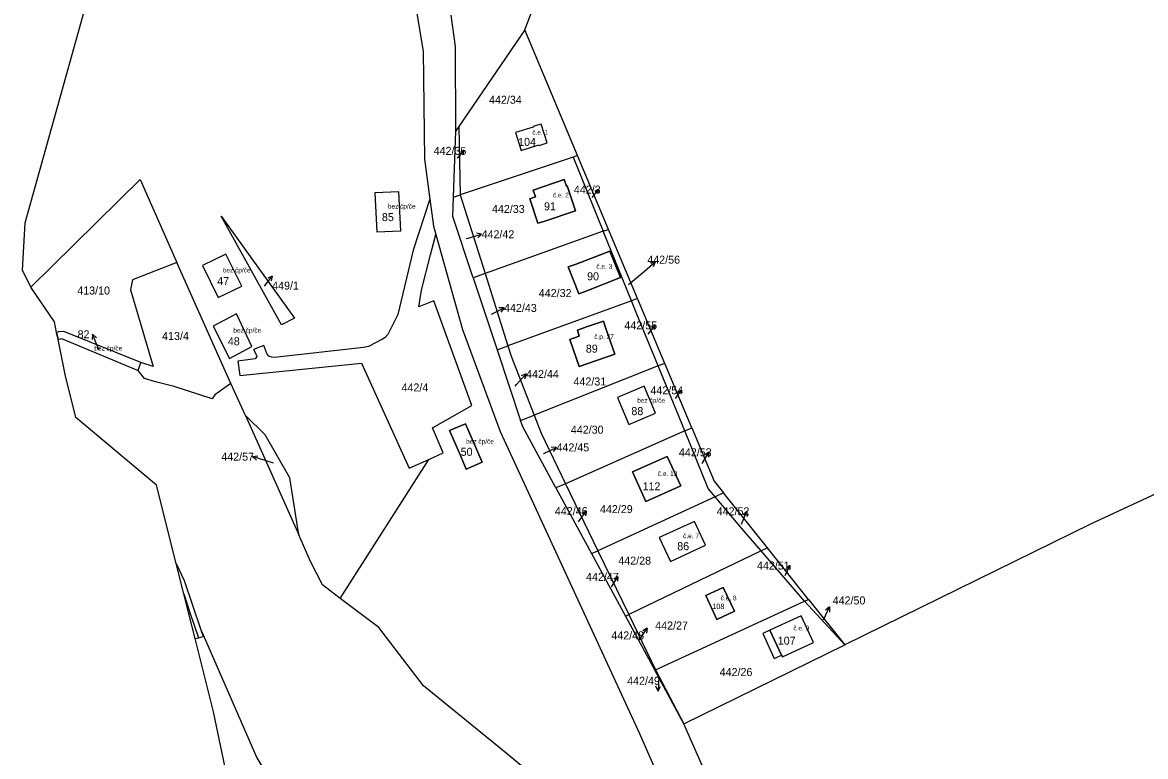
# Model space of a CAD drawing. Extents: x -880531 to -877616, y -1023932 to -1021350.
# Drawn here: x -880276 to -880037.5, y -1022931.1 to -1022775.2 of the extents above; entities that cross this region are included whole.
import ezdxf

# ---------------------------------------------------------------- set-up
doc = ezdxf.new("R2010")
doc.units = 0
for name, color, linetype in [('Definiční body', 7, 'Continuous'), ('Hranice parcel', 7, 'Continuous'), ('Parcelní čísla', 7, 'Continuous'), ('Polygon budovy', 7, 'Continuous'), ('Pop  PČ popisy', 7, 'Continuous'), ('Vnitřní kresba', 7, 'Continuous')]:
    doc.layers.add(name, color=color, linetype=linetype)

msp = doc.modelspace()

# ---------------------------------------------------------------- linework, layer by layer
at = {"layer": 'Hranice parcel'}
for p, q in [((-880169.29, -1022776.73), (-880144.75, -1022711.36)), ((-880169.29, -1022776.73), (-880183.31, -1022797.24)), ((-880158.09, -1022803.43), (-880169.29, -1022776.73)), ((-880184.42, -1022812.24), (-880183.96, -1022798.18)), ((-880183.31, -1022797.24), (-880183.96, -1022798.18)), ((-880183.31, -1022797.24), (-880183.01, -1022811.77)), ((-880159.04, -1022803.75), (-880183.01, -1022811.77)), ((-880158.09, -1022803.43), (-880159.04, -1022803.75)), ((-880159.04, -1022803.75), (-880152.64, -1022819.5)), ((-880151.52, -1022819.1), (-880158.09, -1022803.43)), ((-880184.42, -1022812.24), (-880183.01, -1022811.77)), ((-880183.01, -1022811.77), (-880177.75, -1022828.48)), ((-880152.64, -1022819.5), (-880177.75, -1022828.48)), ((-880152.64, -1022819.5), (-880151.52, -1022819.1)), ((-880146.65, -1022834.24), (-880152.64, -1022819.5)), ((-880145.36, -1022833.76), (-880151.52, -1022819.1)), ((-880231.71, -1022851.8), (-880243.18, -1022826.11)), ((-880177.75, -1022828.48), (-880180.24, -1022829.37)), ((-880177.75, -1022828.48), (-880172.9, -1022843.84)), ((-880180.24, -1022829.37), (-880175.17, -1022844.67)), ((-880145.36, -1022833.76), (-880146.65, -1022834.24)), ((-880139.58, -1022847.55), (-880145.36, -1022833.76)), ((-880146.65, -1022834.24), (-880172.9, -1022843.84)), ((-880268.45, -1022842.51), (-880268.76, -1022841.02)), ((-880266.96, -1022849.92), (-880268.45, -1022842.51)), ((-880175.17, -1022844.67), (-880172.9, -1022843.84)), ((-880175.17, -1022844.67), (-880170.2, -1022859.66)), ((-880251.46, -1022849.04), (-880250.87, -1022847.36)), ((-880248.22, -1022848.2), (-880250.87, -1022847.36)), ((-880140.96, -1022848.09), (-880167.35, -1022858.54)), ((-880139.58, -1022847.55), (-880140.96, -1022848.09)), ((-880133.84, -1022861.23), (-880139.58, -1022847.55)), ((-880250.06, -1022850.8), (-880251.46, -1022849.04)), ((-880228.66, -1022858.63), (-880231.71, -1022851.8)), ((-880228.66, -1022858.63), (-880217.33, -1022883.98)), ((-880170.2, -1022859.66), (-880167.35, -1022858.54)), ((-880135.34, -1022861.89), (-880160.66, -1022873.12)), ((-880135.34, -1022861.89), (-880133.84, -1022861.23)), ((-880208.55, -1022897.51), (-880189.68, -1022867.94)), ((-880243.35, -1022890.07), (-880247.56, -1022873.4)), ((-880160.66, -1022873.12), (-880162.69, -1022874.02)), ((-880162.69, -1022874.02), (-880155.12, -1022887.97)), ((-880160.66, -1022873.12), (-880153.78, -1022887.35)), ((-880128.89, -1022875.87), (-880153.78, -1022887.35)), ((-880127.1, -1022875.05), (-880128.89, -1022875.87)), ((-880117.76, -1022886.76), (-880127.1, -1022875.05)), ((-880155.12, -1022887.97), (-880153.78, -1022887.35)), ((-880155.12, -1022887.97), (-880147.92, -1022901.23)), ((-880153.78, -1022887.35), (-880147.24, -1022900.9)), ((-880119.08, -1022887.39), (-880147.24, -1022900.9)), ((-880117.76, -1022886.76), (-880119.08, -1022887.39)), ((-880109.91, -1022898.06), (-880119.08, -1022887.39)), ((-880109.04, -1022897.67), (-880117.76, -1022886.76)), ((-880200.32, -1022903.66), (-880208.55, -1022897.51)), ((-880141.57, -1022912.65), (-880109.91, -1022898.06)), ((-880109.91, -1022898.06), (-880109.04, -1022897.67)), ((-880101.32, -1022907.34), (-880109.91, -1022898.06)), ((-880109.04, -1022897.67), (-880101.32, -1022907.34)), ((-880147.92, -1022901.23), (-880147.24, -1022900.9)), ((-880147.92, -1022901.23), (-880141.69, -1022912.7)), ((-880147.24, -1022900.9), (-880141.57, -1022912.65)), ((-880135.5, -1022924.1), (-880101.32, -1022907.34)), ((-880141.69, -1022912.7), (-880141.57, -1022912.65)), ((-880135.5, -1022924.1), (-880141.69, -1022912.7)), ((-880141.57, -1022912.65), (-880135.5, -1022924.1)), ((-880231.98, -1022938.01), (-880235.4, -1022921.54))]:
    msp.add_line(p, q, dxfattribs=at)
for points in [[(-880275.46, -1022817.7), (-880256.82, -1022750.96), (-880251.78, -1022710.78), (-880245.5, -1022685.14), (-880239.72, -1022660.82), (-880229.65, -1022581.98)], [(-880192.42, -1022771.99), (-880190.9, -1022781.26), (-880190.62, -1022804.16), (-880189.48, -1022812.67), (-880193.03, -1022823.48), (-880196.3, -1022837.16), (-880198.41, -1022841.43), (-880198.93, -1022842.04), (-880199.51, -1022842.39), (-880202.49, -1022843.95), (-880203.58, -1022844.19), (-880222.49, -1022846.31), (-880223.07, -1022846.27), (-880223.68, -1022846.03), (-880224.08, -1022845.46), (-880224.72, -1022843.76), (-880226.91, -1022844.58), (-880226.29, -1022845.79), (-880226.25, -1022846.13), (-880226.55, -1022846.62), (-880230.28, -1022847.08), (-880229.81, -1022850.13), (-880204.01, -1022847.54), (-880193.87, -1022869.81), (-880189.68, -1022867.94)], [(-880183.96, -1022798.18), (-880184.04, -1022780.28), (-880184.98, -1022773.58)], [(-880171.28, -1022798.52), (-880170.05, -1022802.34), (-880166.3, -1022801.16), (-880166.29, -1022801.25), (-880164.56, -1022800.72), (-880165.85, -1022796.75), (-880167.58, -1022797.28), (-880167.54, -1022797.37), (-880171.28, -1022798.52)], [(-880274.2, -1022831.4), (-880251.03, -1022808.54), (-880243.18, -1022826.11)], [(-880160.92, -1022808.51), (-880160.45, -1022809.89), (-880160.31, -1022809.84), (-880158.51, -1022815.13), (-880165.3, -1022817.42), (-880166.57, -1022817.8), (-880168.26, -1022812.63), (-880167.04, -1022812.2), (-880167.52, -1022810.76), (-880160.92, -1022808.51)], [(-880196.03, -1022811.09), (-880201.13, -1022811.34), (-880200.74, -1022819.64), (-880195.63, -1022819.38), (-880196.03, -1022811.09)], [(-880180.24, -1022829.37), (-880184.56, -1022816.36), (-880184.42, -1022812.24)], [(-880218.2, -1022837.94), (-880220.97, -1022839.34), (-880233.79, -1022816.32), (-880218.2, -1022837.94)], [(-880274.2, -1022831.4), (-880276, -1022827.76), (-880275.46, -1022817.7)], [(-880189.68, -1022867.94), (-880186.63, -1022866.58), (-880188.91, -1022861.28), (-880180.55, -1022856.51), (-880188.62, -1022834.25), (-880191.78, -1022835.57), (-880191.23, -1022832.04), (-880189.34, -1022824.54), (-880188.21, -1022820.18), (-880182.52, -1022840.37), (-880174.52, -1022862.04), (-880144.98, -1022926.17), (-880115.13, -1022994.32), (-880103.69, -1023021.35), (-880083.68, -1023066.92)], [(-880229.43, -1022831.17), (-880232.82, -1022824.35), (-880237.77, -1022826.79), (-880234.44, -1022833.54), (-880229.43, -1022831.17)], [(-880160.09, -1022827.02), (-880158.41, -1022826.5), (-880151.22, -1022823.7), (-880149.01, -1022829.31), (-880156.16, -1022832.13), (-880157.81, -1022832.76), (-880160.09, -1022827.02)], [(-880243.18, -1022826.11), (-880252.64, -1022829.82), (-880253.02, -1022831.97), (-880250.46, -1022840.79), (-880248.22, -1022848.2)], [(-880268.76, -1022841.02), (-880269.22, -1022838.72), (-880274.2, -1022831.4)], [(-880140.96, -1022848.09), (-880145.48, -1022837.11), (-880146.65, -1022834.24)], [(-880227.25, -1022843.97), (-880230.53, -1022837.06), (-880235.53, -1022839.65), (-880232.03, -1022846.5), (-880227.25, -1022843.97)], [(-880158.1, -1022840.53), (-880156.21, -1022839.82), (-880152.58, -1022838.6), (-880152.15, -1022839.94), (-880150.22, -1022845.63), (-880157.78, -1022848.2), (-880159.74, -1022842.47), (-880157.73, -1022841.78), (-880158.1, -1022840.53)], [(-880250.87, -1022847.36), (-880267.24, -1022840.79), (-880268.34, -1022840.87), (-880268.76, -1022841.02)], [(-880268.45, -1022842.51), (-880267.74, -1022842.26), (-880251.46, -1022849.04)], [(-880172.9, -1022843.84), (-880172.21, -1022846.04), (-880167.35, -1022858.54)], [(-880135.34, -1022861.89), (-880138.84, -1022853.26), (-880140.96, -1022848.09)], [(-880247.56, -1022873.4), (-880264.64, -1022859.02), (-880266.96, -1022849.92)], [(-880231.71, -1022851.8), (-880235.16, -1022854.25), (-880235.69, -1022855.06), (-880243.75, -1022852.45), (-880247.77, -1022851.46), (-880250.06, -1022850.8)], [(-880147.22, -1022860.51), (-880141.52, -1022858.1), (-880143.93, -1022852.41), (-880149.63, -1022854.82), (-880147.22, -1022860.51)], [(-880217.33, -1022883.98), (-880219.24, -1022871.89), (-880224.43, -1022862.71), (-880228.66, -1022858.63)], [(-880162.69, -1022874.02), (-880169.75, -1022861.01), (-880170.2, -1022859.66)], [(-880167.35, -1022858.54), (-880165.86, -1022862.36), (-880160.66, -1022873.12)], [(-880183.21, -1022866.61), (-880185.28, -1022861.8), (-880181.92, -1022860.4), (-880178.39, -1022868.57), (-880181.77, -1022870.02), (-880183.21, -1022866.61)], [(-880128.89, -1022875.87), (-880130.37, -1022874.13), (-880135.34, -1022861.89)], [(-880133.84, -1022861.23), (-880129.07, -1022872.59), (-880127.1, -1022875.05)], [(-879968.62, -1022882.91), (-879973.51, -1022875.27), (-879993.92, -1022884.22), (-880013.19, -1022864.99), (-880049.16, -1022881.72), (-880101.32, -1022907.34)], [(-880136.17, -1022873.54), (-880143.6, -1022876.89), (-880146.43, -1022870.61), (-880139.04, -1022867.31), (-880136.17, -1022873.54)], [(-880119.08, -1022887.39), (-880123.18, -1022882.62), (-880128.89, -1022875.87)], [(-880130.91, -1022886.2), (-880133.29, -1022881.11), (-880140.74, -1022884.57), (-880138.39, -1022889.63), (-880130.91, -1022886.2)], [(-880208.55, -1022897.51), (-880212.25, -1022894.59), (-880214.82, -1022889.61), (-880217.33, -1022883.98)], [(-880243.35, -1022890.07), (-880241.64, -1022893.66), (-880238.09, -1022904.18), (-880237.6, -1022905.22), (-880226.25, -1022931.35), (-880223.43, -1022935.9), (-880214.29, -1022936.81), (-880207.9, -1022964), (-880204.04, -1022980.32)], [(-880235.4, -1022921.54), (-880239.33, -1022905.97), (-880240.65, -1022900.77), (-880241.72, -1022896.51), (-880243.35, -1022890.07)], [(-880128.5, -1022901.98), (-880130.87, -1022896.85), (-880127.15, -1022895.13), (-880124.75, -1022900.2), (-880128.5, -1022901.98)], [(-880114.77, -1022909.51), (-880114.61, -1022909.87), (-880108, -1022906.86), (-880110.64, -1022901.17), (-880117.26, -1022904.25), (-880118.77, -1022904.95), (-880116.35, -1022910.23), (-880114.77, -1022909.51)], [(-880129.04, -1023046.29), (-880129.43, -1023044.54), (-880130.69, -1023040.62), (-880137.84, -1023017.32), (-880138.66, -1023014.32), (-880144.53, -1022995.91), (-880145.04, -1022993.98), (-880153.89, -1022965.48), (-880164.21, -1022937.78), (-880165.13, -1022937.04), (-880174.46, -1022929.37), (-880190.85, -1022916.02), (-880200.32, -1022903.66)], [(-880100.73, -1023006.79), (-880107.25, -1022988.21), (-880135.5, -1022924.1)]]:
    msp.add_lwpolyline(points, dxfattribs=at)
at = {"layer": 'Polygon budovy'}
for points in [[(-880171.28, -1022798.52), (-880170.05, -1022802.34), (-880166.3, -1022801.16), (-880166.29, -1022801.25), (-880164.56, -1022800.72), (-880165.85, -1022796.75), (-880167.58, -1022797.28), (-880167.54, -1022797.37)], [(-880160.92, -1022808.51), (-880167.52, -1022810.76), (-880167.04, -1022812.2), (-880168.26, -1022812.63), (-880166.57, -1022817.8), (-880165.3, -1022817.42), (-880158.51, -1022815.13), (-880160.31, -1022809.84), (-880160.45, -1022809.89)], [(-880201.13, -1022811.34), (-880200.74, -1022819.64), (-880195.63, -1022819.38), (-880196.03, -1022811.09)], [(-880237.77, -1022826.79), (-880234.44, -1022833.54), (-880229.43, -1022831.17), (-880232.82, -1022824.35)], [(-880160.09, -1022827.02), (-880157.81, -1022832.76), (-880156.16, -1022832.13), (-880149.01, -1022829.31), (-880151.22, -1022823.7), (-880158.41, -1022826.5)], [(-880235.53, -1022839.65), (-880232.03, -1022846.5), (-880227.25, -1022843.97), (-880230.53, -1022837.06)], [(-880152.58, -1022838.6), (-880156.21, -1022839.82), (-880158.1, -1022840.53), (-880157.73, -1022841.78), (-880159.74, -1022842.47), (-880157.78, -1022848.2), (-880150.22, -1022845.63), (-880152.15, -1022839.94)], [(-880251.46, -1022849.04), (-880250.87, -1022847.36), (-880267.24, -1022840.79), (-880268.34, -1022840.87), (-880268.76, -1022841.02), (-880268.45, -1022842.51), (-880267.74, -1022842.26)], [(-880143.93, -1022852.41), (-880149.63, -1022854.82), (-880147.22, -1022860.51), (-880141.52, -1022858.1)], [(-880181.92, -1022860.4), (-880185.28, -1022861.8), (-880183.21, -1022866.61), (-880181.77, -1022870.02), (-880178.39, -1022868.57)], [(-880146.43, -1022870.61), (-880143.6, -1022876.89), (-880136.17, -1022873.54), (-880139.04, -1022867.31)], [(-880133.29, -1022881.11), (-880140.74, -1022884.57), (-880138.39, -1022889.63), (-880130.91, -1022886.2)], [(-880130.87, -1022896.85), (-880128.5, -1022901.98), (-880124.75, -1022900.2), (-880127.15, -1022895.13)], [(-880108, -1022906.86), (-880110.64, -1022901.17), (-880117.26, -1022904.25), (-880114.77, -1022909.51), (-880114.61, -1022909.87)]]:
    msp.add_lwpolyline(points, close=True, dxfattribs=at)
at = {"layer": 'Pop  PČ popisy'}
for p, q in [((-880183.62, -1022804.01), (-880182.27, -1022802.401)), ((-880182.27, -1022802.401), (-880182.989, -1022802.712)), ((-880182.27, -1022802.401), (-880182.452, -1022803.163)), ((-880155.03, -1022812.33), (-880153.67, -1022810.651)), ((-880153.67, -1022810.651), (-880154.404, -1022810.984)), ((-880153.67, -1022810.651), (-880153.844, -1022811.438)), ((-880181.74, -1022821.07), (-880181.37, -1022820.97)), ((-880181.37, -1022820.97), (-880178.485, -1022820.143)), ((-880178.485, -1022820.143), (-880179.586, -1022819.938)), ((-880178.485, -1022820.143), (-880179.31, -1022820.9)), ((-880143.89, -1022827.95), (-880141.591, -1022826.021)), ((-880141.591, -1022826.021), (-880142.68, -1022826.281)), ((-880141.591, -1022826.021), (-880142.036, -1022827.048)), ((-880224.6, -1022831.18), (-880222.975, -1022829.023)), ((-880222.975, -1022829.023), (-880223.877, -1022829.472)), ((-880222.975, -1022829.023), (-880223.157, -1022830.014)), ((-880147.31, -1022830.82), (-880143.89, -1022827.95)), ((-880176.4, -1022837.13), (-880173.726, -1022835.768)), ((-880173.726, -1022835.768), (-880174.846, -1022835.776)), ((-880173.726, -1022835.768), (-880174.391, -1022836.668)), ((-880176.4, -1022837.13), (-880176.41, -1022837.13)), ((-880143.11, -1022841.35), (-880141.701, -1022839.481)), ((-880141.701, -1022839.481), (-880142.483, -1022839.869)), ((-880141.701, -1022839.481), (-880141.859, -1022840.339)), ((-880261.143, -1022841.378), (-880261.212, -1022842.495)), ((-880259.97, -1022844.14), (-880261.143, -1022841.378)), ((-880261.143, -1022841.378), (-880260.29, -1022842.104)), ((-880259.72, -1022844.72), (-880259.97, -1022844.14)), ((-880171.05, -1022852.04), (-880169.042, -1022849.81)), ((-880169.042, -1022849.81), (-880170.084, -1022850.219)), ((-880169.042, -1022849.81), (-880169.34, -1022850.889)), ((-880171.35, -1022852.37), (-880171.05, -1022852.04)), ((-880137.31, -1022855), (-880136.058, -1022853.276)), ((-880136.058, -1022853.276), (-880136.763, -1022853.642)), ((-880136.058, -1022853.276), (-880136.188, -1022854.06)), ((-880227.124, -1022867.353), (-880226.017, -1022867.186)), ((-880224.27, -1022868.28), (-880227.124, -1022867.353)), ((-880227.124, -1022867.353), (-880226.326, -1022868.138)), ((-880165.35, -1022866.74), (-880165.28, -1022866.71)), ((-880165.28, -1022866.71), (-880162.583, -1022865.394)), ((-880162.583, -1022865.394), (-880163.702, -1022865.383)), ((-880162.583, -1022865.394), (-880163.263, -1022866.284)), ((-880131.61, -1022868.8), (-880130.188, -1022866.433)), ((-880130.188, -1022866.433), (-880131.057, -1022866.986)), ((-880130.188, -1022866.433), (-880130.268, -1022867.46)), ((-880222.71, -1022868.78), (-880224.27, -1022868.28)), ((-880157.91, -1022881.22), (-880156.292, -1022878.909)), ((-880156.292, -1022878.909), (-880157.218, -1022879.41)), ((-880156.292, -1022878.909), (-880156.446, -1022879.95)), ((-880123.25, -1022881.67), (-880122.16, -1022878.971)), ((-880122.16, -1022878.971), (-880122.974, -1022879.69)), ((-880122.16, -1022878.971), (-880122.073, -1022880.054)), ((-880114.04, -1022892.6), (-880113.051, -1022890.479)), ((-880113.051, -1022890.479), (-880113.735, -1022891.021)), ((-880113.051, -1022890.479), (-880113.027, -1022891.352)), ((-880150.87, -1022895.04), (-880149.572, -1022892.879)), ((-880149.572, -1022892.879), (-880150.365, -1022893.384)), ((-880149.572, -1022892.879), (-880149.644, -1022893.817)), ((-880105.9, -1022901.99), (-880104.584, -1022899.293)), ((-880104.584, -1022899.293), (-880105.474, -1022899.973)), ((-880104.584, -1022899.293), (-880104.573, -1022900.412)), ((-880144.94, -1022906.29), (-880143.306, -1022903.773)), ((-880143.306, -1022903.773), (-880144.271, -1022904.34)), ((-880143.306, -1022903.773), (-880143.431, -1022904.886)), ((-880140.86, -1022914.15), (-880141.017, -1022917.147)), ((-880141.017, -1022917.147), (-880141.465, -1022916.121)), ((-880141.017, -1022917.147), (-880140.465, -1022916.173))]:
    msp.add_line(p, q, dxfattribs=at)
at = {"layer": 'Vnitřní kresba'}
for p, q in [((-880189.48, -1022812.67), (-880188.7, -1022818.45)), ((-880188.7, -1022818.45), (-880188.21, -1022820.18)), ((-880241.72, -1022896.51), (-880240.35, -1022900.66)), ((-880240.65, -1022900.77), (-880240.35, -1022900.66)), ((-880240.35, -1022900.66), (-880238.62, -1022905.81)), ((-880238.62, -1022905.81), (-880237.62, -1022905.58)), ((-880238.09, -1022904.18), (-880237.62, -1022905.58)), ((-880114.77, -1022909.51), (-880117.26, -1022904.25)), ((-880239.33, -1022905.97), (-880238.62, -1022905.81))]:
    msp.add_line(p, q, dxfattribs=at)

# ---------------------------------------------------------------- texts
at = {"layer": 'Definiční body'}
for s, p in [('č.e. 1', (-880167.72, -1022799.01)), ('č.e. 2', (-880163.33, -1022812.31)), ('bez čp/če', (-880198.4, -1022814.68)), ('č.e. 3', (-880154.09, -1022827.45)), ('bez čp/če', (-880233.45, -1022828.25)), ('bez čp/če', (-880231.2, -1022841.03)), ('č.p. 27', (-880154.54, -1022842.39)), ('bez čp/če', (-880260.73, -1022844.85)), ('bez čp/če', (-880145.43, -1022855.92)), ('bez čp/če', (-880181.78, -1022864.63)), ('č.e. 13', (-880141.06, -1022871.46)), ('č.e. 7', (-880135.69, -1022884.69)), ('č.e. 8', (-880127.71, -1022897.87)), ('č.e. 9', (-880112.27, -1022904.27))]:
    msp.add_text(s, height=1, dxfattribs=at).set_placement(p)
at = {"layer": 'Parcelní čísla'}
for s, height, p in [('442/34', 1.7, (-880176.91, -1022792.42)), ('104', 1.7, (-880170.725, -1022801.37)), ('442/35', 1.7, (-880188.672, -1022803.27)), ('442/3', 1.7, (-880158.893, -1022811.5)), ('442/33', 1.7, (-880176.284, -1022815.61)), ('91', 1.7, (-880165.231, -1022815.05)), ('85', 1.7, (-880199.66, -1022817.34)), ('442/42', 1.7, (-880178.49, -1022820.99)), ('442/56', 1.7, (-880143.291, -1022826.39)), ('47', 1.7, (-880234.63, -1022830.91)), ('90', 1.7, (-880156.078, -1022829.91)), ('413/10', 1.7, (-880264.36, -1022832.93)), ('449/1', 1.7, (-880222.97, -1022831.888)), ('442/32', 1.7, (-880166.34, -1022833.47)), ('442/43', 1.7, (-880173.72, -1022836.63)), ('442/55', 1.7, (-880148.162, -1022840.33)), ('82', 1.7, (-880264.296, -1022842.24)), ('413/4', 1.7, (-880246.34, -1022842.59)), ('48', 1.7, (-880232.38, -1022843.72)), ('89', 1.7, (-880156.342, -1022845.28)), ('442/44', 1.7, (-880169.03, -1022850.67)), ('442/31', 1.7, (-880158.974, -1022852.25)), ('442/4', 1.7, (-880195.49, -1022853.52)), ('442/54', 1.7, (-880142.625, -1022854.13)), ('88', 1.7, (-880146.67, -1022858.55)), ('442/30', 1.7, (-880159.53, -1022862.49)), ('442/45', 1.7, (-880162.58, -1022866.25)), ('442/57', 1.7, (-880233.773, -1022868.22)), ('50', 1.7, (-880182.93, -1022867.19)), ('442/53', 1.7, (-880136.579, -1022867.3)), ('112', 1.7, (-880144.301, -1022874.52)), ('442/46', 1.7, (-880162.927, -1022879.77)), ('442/29', 1.7, (-880153.345, -1022879.36)), ('442/52', 1.7, (-880128.557, -1022879.82)), ('86', 1.7, (-880136.93, -1022887.24)), ('442/28', 1.7, (-880149.45, -1022890.3)), ('442/51', 1.7, (-880119.99, -1022891.34)), ('442/47', 1.7, (-880156.297, -1022893.75)), ('442/50', 1.7, (-880103.923, -1022898.75)), ('108', 1.139, (-880129.521, -1022899.739)), ('442/27', 1.7, (-880141.61, -1022904.08)), ('442/48', 1.7, (-880150.929, -1022906.18)), ('107', 1.7, (-880115.579, -1022907.3)), ('442/26', 1.7, (-880127.92, -1022913.96)), ('442/49', 1.7, (-880147.569, -1022915.82))]:
    msp.add_text(s, height=height, dxfattribs=at).set_placement(p)

doc.saveas('drawing.dxf')
